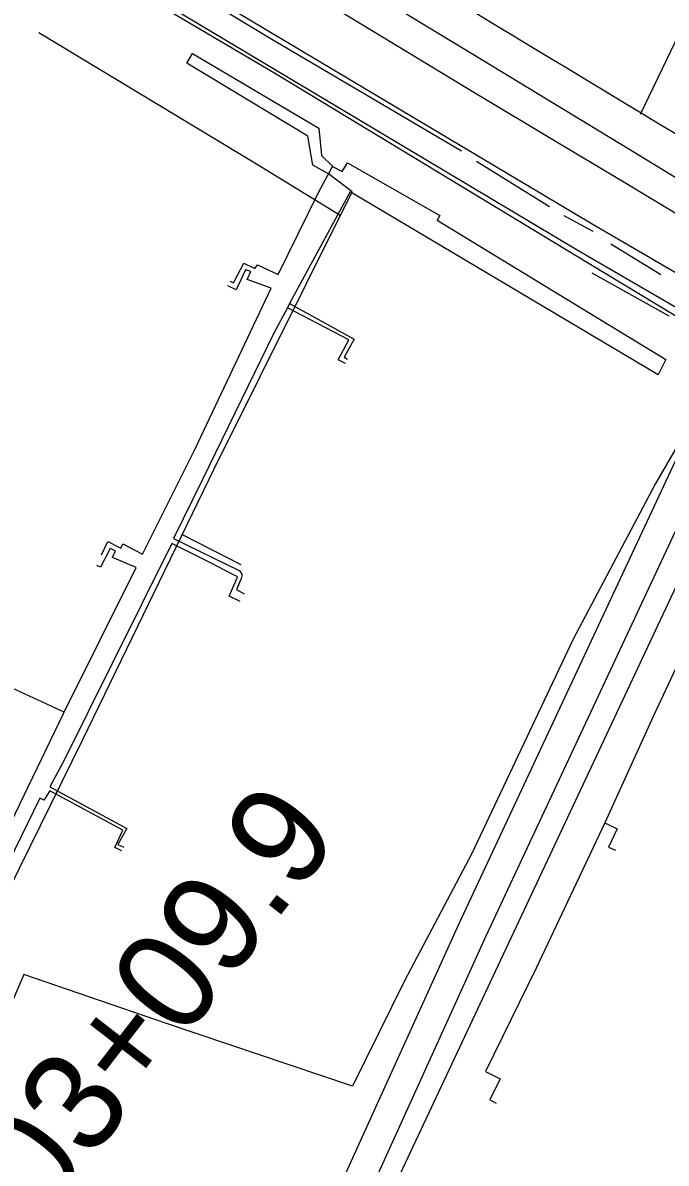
# Model space of a CAD drawing. Extents: x 3704301 to 3742427, y 506229 to 532009.
# Drawn here: x 3715819 to 3716465, y 522452 to 523596 of the extents above; entities that cross this region are included whole.
import ezdxf

# ---------------------------------------------------------------- set-up
doc = ezdxf.new("R2010")
doc.units = 0
for name, color, linetype in [('V-RAIL-TRAK', 7, 'Continuous'), ('V-ROAD-CNTR', 7, 'Continuous'), ('V-SITE-OTLN', 7, 'Continuous'), ('V-SURV-IDEN', 7, 'Continuous'), ('V-TOPO-SHOR', 7, 'Continuous'), ('V-UTIL-LINE', 7, 'Continuous')]:
    doc.layers.add(name, color=color, linetype=linetype)

msp = doc.modelspace()

# ---------------------------------------------------------------- linework, layer by layer
at = {"layer": 'V-RAIL-TRAK'}
msp.add_lwpolyline([(3715570.8, 523950.6), (3715656, 523899.3), (3715741.2, 523847.9), (3715826.4, 523796.5), (3715883.3, 523761.5), (3715940.3, 523726.7), (3715997.4, 523692.2), (3716054.7, 523657.9), (3716112.1, 523623.8), (3716192.7, 523574.6), (3716273.3, 523525.7), (3716354.2, 523477.1), (3716416.5, 523439.9), (3716478.7, 523402.5)], dxfattribs=at)
at = {"layer": 'V-ROAD-CNTR'}
for points in [[(3716439, 523504.6), (3716517.3, 523667.6), (3716789.1, 524259.8), (3716972, 524648.6)], [(3715478.2, 523947.2), (3715612.2, 523862.8), (3715952.5, 523655.9), (3716390.5, 523394.4), (3716543.7, 523305.4)], [(3715850.7, 523682.7), (3715937.1, 523630.2), (3716375.3, 523368.5), (3716530.9, 523278.2)], [(3716530.9, 523278.2), (3716481.5, 523173), (3716256.5, 522692.4), (3716107, 522363)], [(3716556.9, 523263.1), (3716508.6, 523160.2), (3716283.7, 522679.8), (3716134.3, 522350.6)]]:
    msp.add_lwpolyline(points, dxfattribs=at)
msp.add_arc((3823298.2, 700746.6), 206961.4, 238.554724, 238.931243, dxfattribs=at)
at = {"layer": 'V-SITE-OTLN'}
for p, q in [((3715835.6, 523685.5), (3716072.7, 523545.4)), ((3716072.7, 523545.4), (3716387.4, 523354.7)), ((3716387.4, 523354.7), (3716509.2, 523281.2)), ((3716490.3, 523196.8), (3716453.8, 523133.5)), ((3716453.8, 523133.5), (3716371.4, 522977.9)), ((3716371.4, 522977.9), (3716269.4, 522762)), ((3716269.4, 522762), (3716202.3, 522635.2)), ((3715820.3, 522641.5), (3715694.8, 522352.1)), ((3715963.4, 522592.4), (3715820.3, 522641.5)), ((3716202.3, 522635.2), (3716149.8, 522529.5)), ((3716149.8, 522529.5), (3715963.4, 522592.4))]:
    msp.add_line(p, q, dxfattribs=at)
msp.add_lwpolyline([(3716473, 522283.5), (3716459.8, 522283.8), (3716293.7, 522299.2), (3716163.9, 522318.6), (3716156.8, 522322.2), (3716153.9, 522323.7), (3716152.7, 522326.7), (3716152.3, 522330.6), (3716152.3, 522337.5), (3716156.7, 522353.4), (3716516.2, 523119.1)], dxfattribs=at)
at = {"layer": 'V-TOPO-SHOR'}
for p, q in [((3716067.2, 523580.6), (3715558.4, 523891)), ((3716259.2, 523467.5), (3716067.2, 523580.6)), ((3716347.8, 523411.5), (3716274.5, 523457)), ((3716391.3, 523386.9), (3716362.5, 523402.7)), ((3716459.4, 523343.5), (3716409.2, 523374.3)), ((3716390, 523345.4), (3716467.3, 523302.1))]:
    msp.add_line(p, q, dxfattribs=at)
msp.add_lwpolyline([(3716549.3, 523395), (3716427.2, 523469.4), (3716271.4, 523564), (3716128.8, 523650.8), (3715961.7, 523747.9), (3715785.2, 523857.8), (3715634.5, 523954.9)], dxfattribs=at)
at = {"layer": 'V-UTIL-LINE'}
msp.add_line((3715979.2, 523083), (3716038, 523052.8), dxfattribs=at)
for points in [[(3716137.7, 523402.8), (3716053.8, 523454.4), (3715835.1, 523586.2)], [(3716125.9, 523444.7), (3716110.3, 523453.3), (3716105, 523482.5), (3715983.7, 523555.8), (3715989.3, 523565.4), (3716116.2, 523490.7), (3716118.7, 523463), (3716130.4, 523451.8)], [(3716027.3, 523337.1), (3716030.7, 523335.5), (3716041, 523355.2), (3716052, 523349.7), (3716054.5, 523353.4), (3716075.5, 523343.8), (3716116.1, 523426.5), (3716129.9, 523452.1), (3716139.5, 523447.2), (3716144.9, 523455.9), (3716237.7, 523402.8), (3716234.9, 523398.1), (3716464.3, 523258.5), (3716456.7, 523243), (3716147.5, 523426.6), (3716086.9, 523314.5), (3716084.6, 523310.2), (3716070.9, 523284.9), (3715999.5, 523138), (3715970.2, 523078.9), (3716036.4, 523046.8), (3716038.4, 523044.5), (3716038.9, 523042.8), (3716038.9, 523041.3), (3716038.3, 523038.6), (3716033.4, 523027.8), (3716041.1, 523023.4)], [(3715300.4, 522461.1), (3715638, 522381.6), (3715650.5, 522412.1), (3715661.1, 522435.6), (3715667.4, 522447.3), (3715879.5, 522877.3), (3716011.5, 523149.5), (3716149.7, 523426.8), (3716125.9, 523444.7)], [(3715898, 523062.4), (3715904.6, 523076), (3715917.4, 523069.1), (3715919.5, 523073.5), (3715939.3, 523063.1), (3715991.8, 523168.1), (3716068.5, 523329.9), (3716044.2, 523338.8), (3716048.1, 523346.9), (3716042.7, 523348.5), (3716033.3, 523328.2), (3716024.9, 523332.2)], [(3716142.9, 523254.3), (3716135.7, 523258.2), (3716146.2, 523278.1), (3716084.6, 523310.2)], [(3716086.9, 523314.5), (3716151.8, 523278.9), (3716141.6, 523260.8), (3716145.1, 523258.9)], [(3715860.8, 522904.5), (3715643, 523005.1), (3715574.7, 523038.4), (3715490.3, 523078.3), (3715372.6, 523134.2)], [(3715755.6, 522778.8), (3715761.6, 522776.1), (3715770.9, 522796.6), (3715782.2, 522791.2), (3715783.9, 522795.5), (3715803.2, 522785.2), (3715860.1, 522903.2), (3715932.9, 523049.7), (3715909.3, 523059.7), (3715912, 523066.4), (3715906.9, 523068.8), (3715897.2, 523050.1), (3715893.5, 523051.9)], [(3716037.4, 523015.8), (3716026.1, 523020.9), (3716034.5, 523040.2), (3716033.6, 523041.2), (3716030.7, 523042.4), (3716008.1, 523054), (3715968.6, 523073.8), (3715908.8, 522953.4), (3715860.2, 522855.7), (3715846.3, 522829.8), (3715923.5, 522787.9), (3715914.6, 522772), (3715920.4, 522769.1)], [(3716521.8, 523050.2), (3716451.5, 522900.3), (3716403.3, 522793.7), (3716415.4, 522787.7), (3716407, 522769.3), (3716414, 522766.2)], [(3715918.6, 522765.5), (3715911.6, 522769), (3715919.4, 522786.3), (3715846.2, 522825.7), (3715840.3, 522816.4), (3715836.1, 522818.2), (3715766.9, 522676.9), (3715723.8, 522588.7), (3715674.6, 522491.4), (3715640.3, 522507.4), (3715643.4, 522515), (3715638.4, 522516.3), (3715631.8, 522499), (3715625, 522502.2)], [(3716403.3, 522793.7), (3716334.3, 522647.8), (3716283.3, 522544), (3716298.1, 522536.6), (3716287.8, 522515.6), (3716294.1, 522512.5)]]:
    msp.add_lwpolyline(points, dxfattribs=at)

# ---------------------------------------------------------------- texts
at = {"layer": 'V-SURV-IDEN'}
msp.add_text('203+09.9', height=100, rotation=52.2378, dxfattribs=at).set_placement((3715795.4, 522336.3))

doc.saveas('drawing.dxf')
